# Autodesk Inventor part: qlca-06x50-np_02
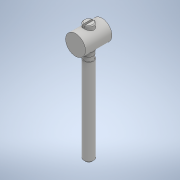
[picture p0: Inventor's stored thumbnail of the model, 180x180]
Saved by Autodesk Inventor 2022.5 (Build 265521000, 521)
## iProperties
Part Number: qlca-06x50-np_02
Material: 一般
Document SubType Name: Modeling
Designer: ImaoCorp
Density: 1 g/cm^3
Appearance: 既定
Author: ImaoCorp
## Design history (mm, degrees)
feature "qlca-06x50-np_02"
node "ソリッド1"
